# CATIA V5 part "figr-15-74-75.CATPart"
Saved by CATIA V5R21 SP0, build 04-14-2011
Part number: Part1
Bounding box of the stored display mesh (mm): x -68.209 to 30, y -98.209 to 60, z 0 to 98
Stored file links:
  D:\CATIA V5R21 E-RESOURCES\CATIA-V5R21\catia-v5r21-prt\c15-catia-v5r20-prt\c15-catia-v5r21-figr-15-66-67.CATPart
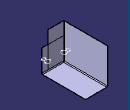
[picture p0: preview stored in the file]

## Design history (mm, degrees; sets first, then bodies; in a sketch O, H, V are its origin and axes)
SheetMetalParameters1: Thickness 1, BendRadius 2, KFactor 0.400515 {= log(min(100,max(20*SheetMetalParameters1.BendRadius,SheetMetalParameters1.Thickness)/SheetMetalParameters1.Thickness))/log(100)/2}, ReliefRadialLength 1, ReliefAxialLength 2, MinimumBendRadius 0
Body1 (main body)
  Sketch1 on xy-plane, origin (0, 0, 0), H (1, 0, 0), V (0, 1, 0)
    line L1 (-30, 60) -> (30, 60)
    line L2 (30, 60) -> (30, -60)
    line L3 (30, -60) -> (-30, -60)
    line L4 (-30, -60) -> (-30, 60)
    length L2 = 120
    length L1 = 60
    distance V L2 = 30
    distance H L1 = 60
    horizontal: L1 H, L3 H
    vertical: L2 V, L4 V
  Wall1: Thickness 1, Profile Sketch1
  d_NewWallOnEdge1: NewWallOnEdge_Edge edge [face of Wall1 | face of Wall1], NewWallOnEdge_Length 98, NewWallOnEdge_HeightLimitOffset 0, NewWallOnEdge_WidthOffset1 0, NewWallOnEdge_WidthOffset2 0, NewWallOnEdge_Angle 90, NewWallOnEdge_BendRadiusValue 2 {= SheetMetalParameters1.BendRadius}, NewWallOnEdge_BendTable SheetMetalParameters1, KFacteur 0.400515 {= log(min(100,max(20*d_NewWallOnEdge1.Radius,SheetMetalParameters1.Thickness)/SheetMetalParameters1.Thickness))/log(100)/2}
  d_NewWallOnEdge2: NewWallOnEdge_Edge edge [face of Wall1 | face of Wall1], NewWallOnEdge_Length 63, NewWallOnEdge_HeightLimitOffset 0, NewWallOnEdge_WidthOffset1 0, NewWallOnEdge_WidthOffset2 0, NewWallOnEdge_Angle 90, NewWallOnEdge_BendRadiusValue 2 {= SheetMetalParameters1.BendRadius}, NewWallOnEdge_BendTable SheetMetalParameters1, KFacteur 0.400515 {= log(min(100,max(20*d_NewWallOnEdge2.Radius,SheetMetalParameters1.Thickness)/SheetMetalParameters1.Thickness))/log(100)/2}
  d_NewWallOnEdge3: NewWallOnEdge_Edge edge [face of d_NewWallOnEdge1 | face of d_NewWallOnEdge1], NewWallOnEdge_Length 44, NewWallOnEdge_HeightLimitOffset 0, NewWallOnEdge_WidthOffset1 0, NewWallOnEdge_WidthOffset2 0, NewWallOnEdge_Angle 90, NewWallOnEdge_BendRadiusValue 2 {= SheetMetalParameters1.BendRadius}, NewWallOnEdge_BendTable SheetMetalParameters1, KFacteur 0.400515 {= log(min(100,max(20*d_NewWallOnEdge3.Radius,SheetMetalParameters1.Thickness)/SheetMetalParameters1.Thickness))/log(100)/2}
  Sketch2 on face of d_NewWallOnEdge3, origin (0, -60, 0), H (-1, 0, 0), V (0, 0, 1)
    circle A1 centre (8.1625, 34.9685) radius 4.4696
    circle A2 centre (8.1625, 23.754) radius 6.7449
    tangency: A2 A1
  SHMMapping1: CATSHMMappingContext d_NewWallOnEdge3, CATSHMMappingObject Sketch2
